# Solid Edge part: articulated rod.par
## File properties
Author: Robert a Rhodes jr
Template: Normal.par
Last saved by: CADCIM
Revision: 9
Application: Solid Edge
Accuracy: 0.99
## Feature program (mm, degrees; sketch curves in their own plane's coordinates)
pattern "unnamed Pattern 1"
pattern "unnamed Pattern 2"
Other named dimensions: "Hole_2": Diameter = 15 mm
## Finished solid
Body 1: solid body, 26 faces, 56 edges, 32 vertices.
  Faces by surface: plane 14, cylinder 12
  Edges by curve: circle 28, line 28
Bounding box of the edges (mm): 207.500 x 35.000 x 42.000, from (-101, -17.5, -21) to (106.5, 17.5, 21).
Cylindrical faces by radius (mm): R6.35 x4, R7.5 x1, R12 x2, R17.5 x1, R24 x4
Planar faces by outward normal: +y 3, +z 4, -y 3, -z 4
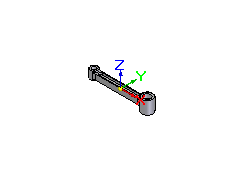
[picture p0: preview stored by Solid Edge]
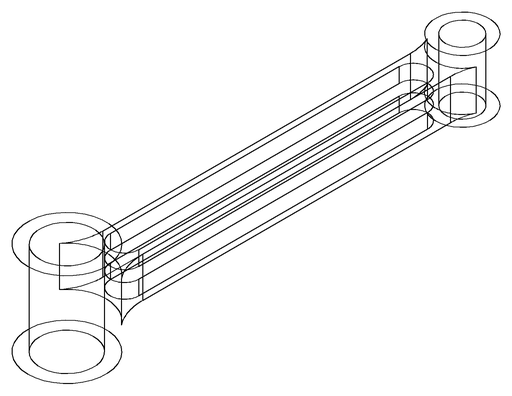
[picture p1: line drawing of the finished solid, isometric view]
